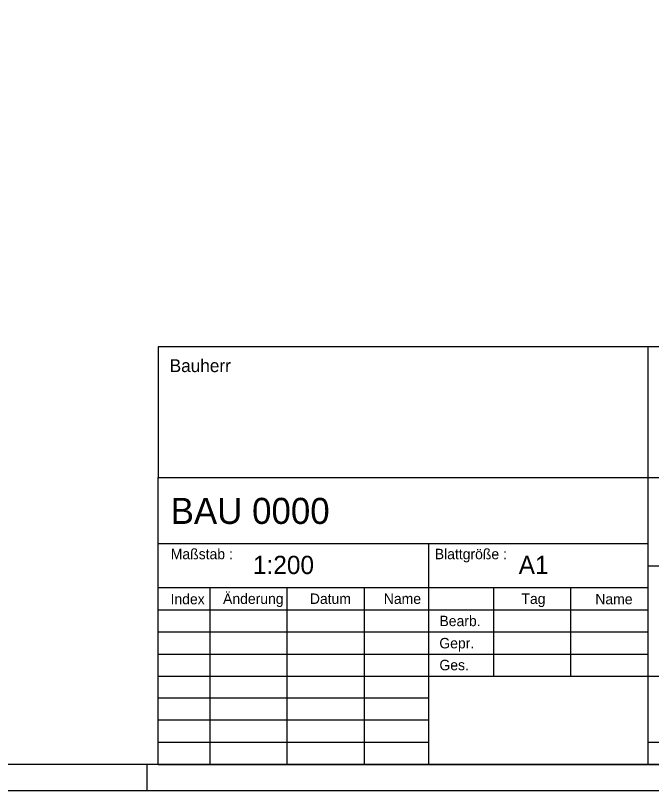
# Model space of a CAD drawing. Extents: x 0 to 168, y 0 to 119.
# Drawn here: x 126.15 to 150.53, y 0 to 29.7 of the extents above; entities that cross this region are included whole.
import ezdxf

# ---------------------------------------------------------------- set-up
doc = ezdxf.new("R2010")
doc.units = 0
doc.layers.add('90_Plankopf', color=7, linetype='Continuous')

msp = doc.modelspace()

# ---------------------------------------------------------------- linework, layer by layer
at = {"layer": '90_Plankopf'}
for p, q in [((167.2, 16.998), (131.624, 16.998)), ((131.624, 16.998), (131.624, 11.998)), ((150.4, 11.998), (150.4, 16.998)), ((131.624, 11.998), (167.2, 11.998)), ((131.624, 1), (131.624, 11.998)), ((131.624, 11.998), (167.2, 11.998)), ((150.4, 1), (150.4, 11.998)), ((131.624, 9.46), (150.4, 9.46)), ((142, 1), (142, 9.46)), ((150.4, 8.614), (167.2, 8.614)), ((131.624, 7.774), (150.4, 7.774)), ((133.6, 7.768), (133.6, 1)), ((136.565, 1), (136.565, 7.768)), ((139.53, 1), (139.53, 7.768)), ((144.471, 7.768), (144.471, 4.384)), ((147.436, 4.384), (147.436, 7.768)), ((131.624, 6.926), (150.4, 6.926)), ((131.624, 6.076), (150.4, 6.076)), ((131.624, 5.23), (150.4, 5.23)), ((131.624, 4.384), (150.4, 4.384)), ((131.624, 4.384), (150.4, 4.384)), ((142, 4.384), (150.4, 4.384)), ((150.4, 4.384), (167.2, 4.384)), ((142, 3.538), (131.624, 3.538)), ((142, 2.692), (131.624, 2.692)), ((131.624, 1.846), (142, 1.846)), ((150.4, 1.846), (167.2, 1.846)), ((131.2, 0), (131.2, 1)), ((167.2, 1), (131.624, 1)), ((131.624, 1), (142, 1)), ((133.96, 1), (167.2, 1)), ((133.96, 1), (167.2, 1))]:
    msp.add_line(p, q, dxfattribs=at)
for points in [[(0, 0), (168.2, 0), (168.2, 118.8), (0, 118.8)], [(5, 117.8), (167.2, 117.8), (167.2, 1), (5, 1)]]:
    msp.add_lwpolyline(points, close=True, dxfattribs=at)

# ---------------------------------------------------------------- texts
for s, height, p in [('Bauherr', 0.4927, (132.061, 16.035)), ('BAU 0000      ', 1, (132.098, 10.215)), ('Maßstab :', 0.4, (132.103, 8.863)), ('Blattgröße :', 0.39998, (142.223, 8.863)), ('1:200    ', 0.7, (135.252, 8.294)), ('A1       ', 0.7, (145.44, 8.294)), ('Index', 0.4, (132.094, 7.135)), ('Änderung', 0.4, (134.107, 7.15)), ('Datum', 0.4, (137.434, 7.15)), ('Name', 0.4, (140.269, 7.15)), ('Tag', 0.4, (145.545, 7.15)), ('Name', 0.4, (148.378, 7.135)), ('Bearb.', 0.4, (142.403, 6.298)), ('Gepr.', 0.4, (142.398, 5.446)), ('Ges.', 0.4, (142.401, 4.609))]:
    msp.add_text(s, height=height, dxfattribs=at).set_placement(p)

doc.saveas('drawing.dxf')
